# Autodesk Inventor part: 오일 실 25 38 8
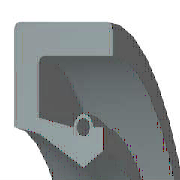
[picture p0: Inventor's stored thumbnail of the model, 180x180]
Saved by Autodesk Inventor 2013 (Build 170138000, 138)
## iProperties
IsCustomPart: 1
Created: 2012-02
Part Number: 오일 실 25 38 8
Material: 고무
Description: 오일-실
Document SubType Name: Modeling
Standard: KS B 2804
Designer: mduedu
Standards Organization: KS
Language: ko-KR
Size Designation: S - 25 38 8
Categories: <MemberInstance><Categories><Category DisplayName="샤프트 부품" InternalName="7f7aeb1f-a693-4053-b835-cee3144e0d98" Mnemonic="SHFT"><Category DisplayName="실링" Intern
Density: 0.93 g/cm^3
Author: mduedu
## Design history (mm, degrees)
revolve "본체" stored, may be unused: angle "d17" = 90 deg
revolve "스프링1" stored, may be unused: angle "d18" = 90 deg
body "Solid1"
sketch "스케치1"
  geometry: L1 (0, 19)-(8, 19); L2 (8, 19)-(8, 17.75); L3 (8, 17.75)-(1.75, 17.75); L4 (0, 19)-(0, 14.6); L5 (0, 14.6)-(1.75, 14.25); L6 (1.75, 14.25)-(4.9, 12.5); L7 (4.9, 12.5)-(0, 12.5); L8 (6.3, 13.375)-(6.3, 14.6); L9 (0, 0)-(9.586, 0) reference; L10 (4.9, 12.5)-(6.3, 13.375); L11 (0, 18)-(0, -3) reference; L12 (-1.917, 0)-(11.503, 0) reference; L13 (4.2, 14.6)-(1.75, 15.09); L14 (1.75, 15.09)-(1.75, 17.75); L15 (6.3, 14.6)-(5.6, 14.6); C1 r 0.455 at (4.9, 14.6); A1 r 0.7 centre (4.9, 14.6) between (5.6, 14.6) and (4.2, 14.6)
  constraints: 26 end point, 5 horizontal alignment, 4 perpendicular, 2 centre point, 2 collinear, 2 horizontal, 2 parallel, 2 point on circle, 2 point on line, 2 vertical alignment, 1 coincident
  dimensions: "d0" = 38 diameter of L1 L9 (= SD2); "d1" = 26.75 diameter of L8.start L9 (= ABDM); "d2" = 1.25 distance of L1.end L2.end (computed from SD); "d3" = 0.91 diameter of C1 (= SPDI); "d4" = 1.4 diameter of A1 (= SPDA); "d5" = 25 diameter of L6.end L9 (= NND); "d6" = 28.5 diameter of L5.end L9 (= TKDM); "d7" = 29.2 diameter of L4.end L9 (= HLDM); "d8" = 4.9 distance from line of C1.centre L4 (= SPDST); "d9" = 6.3 distance between parallel lines of L8 L4 (= SDI); "d10" = 8 distance between parallel lines of L2 L4 (= SWDT); "d12" = 1.75 distance between parallel lines of L14 L4 (= SD)
fillet "모깎기1" dims "d11" = 0.5 (= RR)
other parameters: "SD2" = 38 [user parameter; used in 1 equation term], "SWDT" = 8 [user parameter; used in 1 equation term], "RR" = 0.5 [user parameter; used in 1 equation term], "SD" = 1.75 [user parameter; used in 2 equation terms], "NND" = 25 [user parameter; used in 1 equation term], "SPDA" = 1.4 [user parameter; used in 1 equation term], "SPDI" = 0.91 [user parameter; used in 1 equation term], "TKDM" = 28.5 [user parameter; used in 1 equation term], "HLDM" = 29.2 [user parameter; used in 1 equation term], "ABDM" = 26.75 [user parameter; used in 1 equation term], "SDI" = 6.3 [user parameter; used in 1 equation term], "SPDST" = 4.9 [user parameter; used in 1 equation term], "d13" = 0, "d14" = 0, "d15" = 0, "LAB" = 0.35 [user parameter]
